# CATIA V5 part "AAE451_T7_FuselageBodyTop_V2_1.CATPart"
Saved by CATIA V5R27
Part number: Part8
Bounding box of the stored display mesh (mm): x -98.453 to 98.453, y -250 to 100, z 0 to 59.995
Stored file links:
  W:\AAE 451\AAE451_T7_FuselageAssemble_V2\AAE451_T7_FuselageBodyTop_V2_1.CATPart
  W:\AAE 451\AAE451_T7_FuselageBody.CATPart
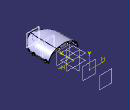
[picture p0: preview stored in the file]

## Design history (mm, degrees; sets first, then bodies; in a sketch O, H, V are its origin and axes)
Body1 (main body)
Body2
  Plane1: type Offset, RefPlane zx-plane, Offset 250, reversed
  Plane2: type Offset, RefPlane zx-plane, Offset 100
  Sketch1 on Plane1, origin (0, -250, 0), H (-1, 0, 0), V (0, 0, 1)
    circle A1 centre (0, 0) radius 30
    distance O A1 = 30
  Plane3: type Offset, RefPlane zx-plane, Offset 150, reversed
  Sketch2 on Plane2, origin (0, 100, 0), H (-1, 0, 0), V (0, 0, 1)
    construction line L1 (0, 60) -> (0, -40)
    point P1 (0, 60)
    construction line L2 (-92.2886, 30) -> (87.7114, 30)
    point P5 (0, 30)
    coincidence: P1 V, P5 L2, P5 L1
    vertical: L1 V
    horizontal: L2 H
  Sketch3 on Plane2, origin (0, 100, 0), H (-1, 0, 0), V (0, 0, 1)
    construction line L1 (0, -100) -> (0, 70)
    point P1 (0, -100)
    construction line L2 (-103.4986, 30) -> (116.5014, 30)
    point P5 (0, 30)
    point P6 (0, 60)
    construction line L3 (-60, 60) -> (60, 60)
    point P7 (-60, 60)
    reference projected curve E1 from Sketch4.E1
    ellipse A1 centre (0, 60) semi-axes 60, 35 rotation 180 from (-60, 60) to (60, 60)
    point P8 (-60, 60)
    point P9 (60, 60)
    point P10 (60, 60)
    point P11 (-60, 60)
    ellipse A2 centre (0, 60) semi-axes 60, 35 rotation 180 from (-60, 60) to (60, 60)
    "Radius" A1 = 60
    "Radius" A1 = 35
    coincidence: P1 V, P5 L2, P5 L1, P6 L1, A1 P7, P7 L3, P6 L3
    vertical: L1 V
    horizontal: L2 H, L3 H, A1 H
    tangency: L3 E1
    symmetry: P9 P10 L3, P8 P11 L3, A1 A2 L3
  Sketch4 on zx-plane, origin (0, 0, 0), H (-1, 0, 0), V (0, 0, 1)
    projected curve E1 from Sketch5.A1
  Sketch5 on Plane3, origin (0, -150, 0), H (-1, 0, 0), V (0, 0, 1)
    construction line L1 (50, 50) -> (50, -50)
    construction line L2 (50, -50) -> (-50, -50)
    construction line L3 (-50, -50) -> (-50, 50)
    construction line L4 (-50, 50) -> (50, 50)
    point P1 (50, 50)
    point P2 (50, -50)
    point P3 (-50, -50)
    point P4 (-50, 50)
    construction line L5 (0, -60) -> (0, 90)
    point P5 (0, -60)
    construction line L6 (-100, 0) -> (110, 0)
    point P7 (-100, 0)
    ellipse A1 centre (0, 0) semi-axes 90.4534, 60 rotation 0
    point P9 (0, 60)
    length L1 = 100
    length L4 = 100
    vertical: L1 V, L3 V, L5 V
    horizontal: L2 H, L4 H, L6 H, A1 H
    equidistance: L1 L3 O, L2 L4 O
    coincidence: P5 V, P7 H, P9 L5, A1 P9, P2 A1, A1 P3, P1 A1, P4 A1
    parallelism: A1 L6
  Loft1: solid, Sections (Sketch3; Sketch4; Sketch5; Sketch1)
  Sketch6 on face of Loft1, origin (0, 100, 0), H (-1, 0, 0), V (0, 0, 1)
    line L1 (-70, 95) -> (70, 95)
    line L2 (70, 95) -> (70, 60)
    line L3 (70, 60) -> (-70, 60)
    line L4 (-70, 60) -> (-70, 95)
    reference projected curve E1 from edge [face of Loft1 | face of Loft1]
    construction line L5 (-60, 60) -> (60, 60)
    length L1 = 140
    horizontal: L1 H, L3 H, L5 H
    vertical: L2 V, L4 V
    coincidence: L3 L5
    tangency: L1 E1
    symmetry: L4 L2 V
  Pocket1: profile Sketch6, direction (0, -1, 0), through (limit type 6)
  Plane4: type Offset, RefPlane Plane2, Offset 100
  Sketch7 on Plane4, origin (0, 200, 0), H (-1, 0, 0), V (0, 0, 1)
    projected line E2 (-60, 60) -> (60, 60) from edge [face of Loft1 | face of Pocket1 from Sketch6.L3]
  Pad1: profile Sketch7, direction (0, 1, 0), up to the existing solid (limit type 3)
  Sketch8 on face of Loft1, origin (0, -250, 0), H (1, 0, 0), V (0, 0, 1)
    line L1 (-100, 0) -> (100, 0)
    point P1 (-100, 0)
    point P2 (100, 0)
    line L2 (-64.2043, -62) -> (64.2043, -62)
    point P3 (-64.2043, -62)
    point P4 (64.2043, -62)
    line L3 (100, 0) -> (64.2043, -62)
    line L4 (-100, 0) -> (-64.2043, -62)
    angle L4 L1 = 60
    distance L1 L2 = 62
    length L1 = 200
    horizontal: L1 H, L2 H
    symmetry: P2 P1 V, P3 P4 V
    coincidence: L1 H
  Pocket2: profile Sketch8, direction (0, 1, 0), through (limit type 6)
  Sketch9 on face of Pocket2 from Sketch8.L1, origin (0, 0, 0), H (1, 0, 0), V (0, -1, 0)
  Sketch10 on start face of Pad1, origin (0, 200, 0), H (-1, 0, 0), V (0, 0, 1)
    circle A1 centre (26, 46.5) radius 6.85
    point P1 (26, 46.5)
    circle A2 centre (-26, 46.5) radius 6.85
    reference projected line E1 (60, 60) -> (-60, 60) from edge [face of Pad1 | start face of Pad1]
    radius A1 = 6.85
    distance V P1 = 26
    distance E1 P1 = 13.5
    symmetry: A2 A1 V
  Pocket3: profile Sketch10, direction (0, -1, 0), length 300
  Plane5 "MOTOR": type Offset, RefPlane Plane1, Offset 4
  Plane6 "BATTERY": type Offset, RefPlane Plane1, Offset 88.5
  Shell1: ExtOffset 0, Face face of Pocket2 from Sketch8.L1, IntOffset 2
  Plane7: type Offset, RefPlane xy-plane, Offset 40
  Sketch11 on Plane7, origin (0, 0, 40), H (1, 0, 0), V (0, 1, 0)
    line L1 (69.2382, 78.9472) -> (-67.3756, 82.6205)
  Pad2: profile Sketch11, direction (0, 0, 1), up to the existing solid (limit type 2)
  Sketch12 on face of Pocket2 from Sketch8.L1, origin (0, 0, 0), H (1, 0, 0), V (0, -1, 0)
    arc A1 centre (-93.4534, 150) radius 5 from (-93.4534, 155) to (-93.4534, 145) ccw
    point P1 (-93.4534, 150)
    line L1 (-93.4534, 145) -> (-88.4534, 145)
    line L2 (-88.4534, 145) -> (-88.4534, 155)
    line L3 (-88.4534, 155) -> (-93.4534, 155)
    reference projected curve E1 from edge [face of Shell1 | face of Pocket2 from Sketch8.L1]
    reference intersected line E2 through (0, 150) direction (1, 0) from Plane3
    distance P1 L2 = 5
    distance L3 L1 = 10
    horizontal: L1 H, L3 H
    tangency: L2 E1, L1 A1, L3 A1
    coincidence: E2 P1
    vertical: L2 V
  Pad3: profile Sketch12, direction (0, 0, 1), length 10
  Sketch13 on face of Pad3, origin (0, 0, 0), H (1, 0, 0), V (0, -1, 0)
    circle A1 centre (-93.4534, 150) radius 2.5
    reference projected arc E1 centre (-93.4534, 150) radius 5 from (-93.4534, 155) to (-93.4534, 145) ccw from edge [face of Pad3 from Sketch12.A1 | start face of Pad3]
    radius A1 = 2.5
    concentricity: A1 E1
  Pocket4: profile Sketch13, direction (0, 0, 1), through (limit type 6)
  RectPattern1: of Pad3, direction 1 instances 3, spacing 75, along yz-plane
  RectPattern2: of Pocket4, direction 1 instances 3, spacing 75, along yz-plane
  Mirror1: of RectPattern1, about yz-plane
  Mirror2: of RectPattern2, about yz-plane
  Plane8 "PRINT CAPACITY": type Offset, RefPlane Plane4, Offset 260, reversed
  Sketch14 on start face of Pad1, origin (0, 200, 0), H (-1, 0, 0), V (0, 0, 1)
    projected circle E1 centre (26, 46.5) radius 6.85 from edge [start face of Pad1 | face of Pocket3 from Sketch10.A1]
    projected circle E2 centre (-26, 46.5) radius 6.85 from edge [start face of Pad1 | face of Pocket3 from Sketch10.A2]
  Pocket5: profile Sketch14, direction (0, -1, 0), length 300
  Sketch15 on Plane8, origin (0, -60, 0), H (-1, 0, 0), V (0, 0, 1)
    point P1 (0, 30)
    line L1 (132.2054, 60) -> (132.2054, 0)
    line L2 (132.2054, 0) -> (-132.2054, 0)
    line L3 (-132.2054, 0) -> (-132.2054, 60)
    line L4 (-132.2054, 60) -> (132.2054, 60)
    reference projected line E1 (60, 60) -> (-60, 60) from edge [face of Pad1 from Sketch7.E2 | start face of Pad1]
    vertical: L1 V, L3 V
    horizontal: L2 H, L4 H
    equidistance: L1 L3 P1, L2 L4 P1
    coincidence: L4 E1, L2 H
    symmetry: L3 L1 V
  Pocket6: profile Sketch15, direction (0, 1, 0), through (limit type 6)
  Sketch16 on Plane5, origin (0, -246, 0), H (-1, 0, 0), V (0, 0, 1)
    arc A1 centre (0, 0) radius 30 from (30, 0) to (-30, 0) ccw
    line L1 (-30, 0) -> (30, 0)
    point P1 (30, 0)
    point P3 (30, 0)
    radius A1 = 30
    coincidence: L1 H, P1 P3
  Pad4: profile Sketch16, direction (0, 1, 0), up to the existing solid (limit type 3)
